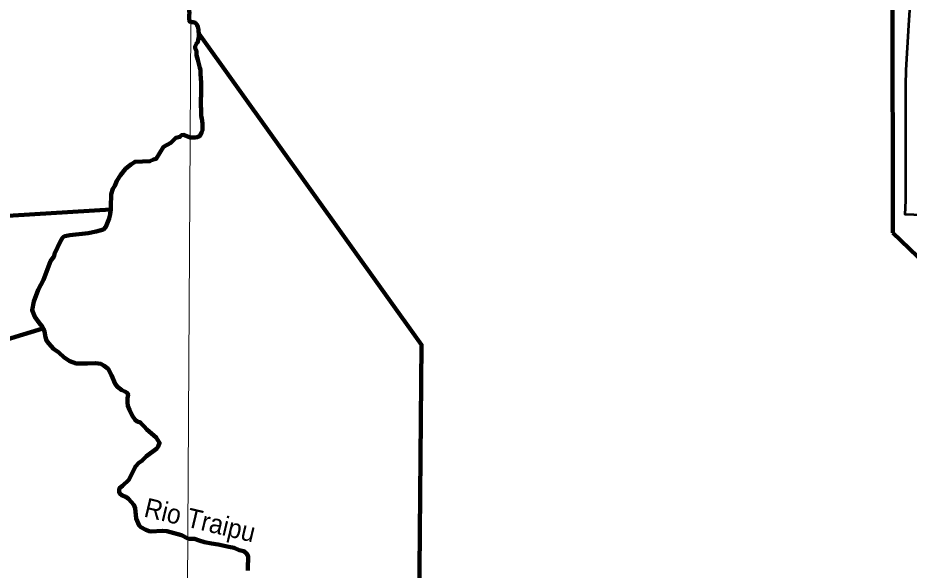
# Model space of a CAD drawing. Extents: x -1643653 to 4543381, y 1624270 to 13878484.
# Drawn here: x 714916 to 738063, y 8908730 to 8923080 of the extents above; entities that cross this region are included whole.
import ezdxf
from ezdxf.enums import TextEntityAlignment as Align

# ---------------------------------------------------------------- set-up
doc = ezdxf.new("R2010")
doc.units = 0
doc.header["$LTSCALE"] = 200
for name, color, linetype, lineweight in [('1', 7, 'Continuous', 13), ('24', 7, 'Continuous', 25), ('26', 7, 'Continuous', 106), ('28', 7, 'Continuous', 53), ('53', 7, 'Continuous', 106), ('60', 7, 'Continuous', 13), ('9', 7, 'Continuous', 90)]:
    doc.layers.add(name, color=color, linetype=linetype, lineweight=lineweight)
doc.layers.add('49', color=7, linetype='Continuous')

msp = doc.modelspace()

# ---------------------------------------------------------------- linework, layer by layer
at = {"layer": '1'}
msp.add_lwpolyline([(719978.9, 9023574.5), (719561.6, 8949232.2), (719215.6, 8890710.6)], dxfattribs=at)
at = {"layer": '24', "lineweight": 53}
for points in [[(719358.6, 8923326.6), (719372.1, 8923197), (719363, 8923148), (719367.5, 8923075.7), (719375.1, 8922983.9), (719405.7, 8922963.6)], [(719405.7, 8922963.6), (719467, 8922963.5), (719527.9, 8922947.8), (719573.3, 8922891.5), (719593.3, 8922845.5), (719608.1, 8922779.2), (719607.8, 8922728.2), (719612.5, 8922677.3), (719617.2, 8922621.2), (719616.8, 8922565.2), (719596.1, 8922509.3), (719590.6, 8922448.2), (719555.4, 8922413.6), (719520.2, 8922331.3), (719524.1, 8922280.4), (719553.5, 8922224.3), (719553.1, 8922173.4), (719552.7, 8922107.2), (719587.5, 8921989.8), (719627.2, 8921846.9), (719642, 8921780.6), (719656.8, 8921724.4), (719661.5, 8921663.3), (719661, 8921586.9), (719665.7, 8921535.9), (719670.4, 8921479.9), (719675.1, 8921423.8), (719674.7, 8921357.6), (719674.3, 8921301.6), (719673.9, 8921240.4), (719673.5, 8921184.4), (719673.1, 8921123.3), (719672.6, 8921057.1), (719672.1, 8920985.7), (719671.7, 8920929.7), (719671.3, 8920863.5), (719670.7, 8920782), (719675.3, 8920705.6), (719674.8, 8920644.4), (719674.4, 8920578.2), (719679.1, 8920527.2), (719693.9, 8920460.9), (719703.7, 8920399.8), (719708.3, 8920328.4), (719707.9, 8920272.4), (719707.5, 8920211.2), (719707.1, 8920155.2), (719681.3, 8920099.3), (719660.5, 8920043.4), (719629.7, 8920002.9), (719573.7, 8919982.9), (719517.6, 8919973.1), (719446.4, 8919968.4), (719388, 8919968.8)], [(719388, 8919968.8), (719217, 8920039.9), (719168.4, 8920030.7), (719126.8, 8919983.7), (719021.9, 8919963.8), (718888.7, 8919829.8), (718888.7, 8919829.8)], [(718888.7, 8919829.8), (718698.9, 8919728.1), (718508.1, 8919414.8), (718441.7, 8919396.1), (718342.3, 8919352.7), (717962.6, 8919341.8), (717850.2, 8919266.6), (717715.4, 8919155.6), (717584.3, 8918993), (717484.9, 8918843.2), (717433.5, 8918714), (717386.5, 8918633.6), (717343.6, 8918502.1), (717334.1, 8918168.6), (717316.4, 8917983.3), (717287.5, 8917863.5), (717202.1, 8917652.5), (717139.9, 8917584.2), (716949.9, 8917526.3), (716744.6, 8917482.9), (716262.7, 8917433.2), (716138.9, 8917405.7), (716105.4, 8917390.9), (716076.8, 8917365.2), (716021.3, 8917281.8), (715870.4, 8916945.9), (715855.1, 8916891.8), (715765.5, 8916761), (715585.2, 8916273.3), (715439.9, 8916014.5), (715332.6, 8915712.1), (715285.6, 8915483), (715360.4, 8915309.1), (715466.5, 8915151.7), (715544.8, 8915057.8), (715568.8, 8915033.9), (715582.8, 8914999.5)], [(715582.8, 8914999.5), (715607.3, 8914926.5), (715630.8, 8914782.1), (715664.2, 8914698.4), (715720.4, 8914621.3), (715841.4, 8914484.8), (715976.3, 8914382.9), (716121.9, 8914251.7), (716262.7, 8914158.2), (716430.6, 8914102.4), (716723.3, 8914098.2), (716931, 8914106.3), (717067.3, 8914089.8), (717160, 8914040), (717258.6, 8913960.8), (717350.2, 8913798.9), (717444.9, 8913569.6), (717500.7, 8913495.3), (717620.4, 8913403.7), (717696.9, 8913374.6), (717753.4, 8913338.3), (717771.3, 8913315.3), (717779.7, 8913284.7), (717767.4, 8913198.7), (717765.2, 8913088.6), (717776, 8913003.3), (717816.4, 8912891.5), (717881.6, 8912752), (717959.7, 8912633.8), (718012.2, 8912595.1), (718103.9, 8912566), (718108.4, 8912552.9), (718200.6, 8912462.7), (718263.8, 8912388), (718510.9, 8912180.7), (718595.9, 8912042.5), (718559.6, 8911942), (718525.1, 8911895.3), (718256.7, 8911695.7), (718139.8, 8911569.1), (718058.8, 8911518.2), (717971, 8911425.9), (717799.8, 8911079.5), (717637.2, 8910919.9), (717559.9, 8910863.9), (717548.7, 8910844.9), (717546.6, 8910765.8), (717564.2, 8910723.9), (717629.5, 8910673.2), (717717.9, 8910632.5), (717786.1, 8910583.9), (717932.5, 8910426.1), (717961.9, 8910338.5), (717987.1, 8910076.6), (718063.3, 8909892.7), (718110.2, 8909851.7), (718240.9, 8909774.5), (718323.8, 8909744.9), (718380.9, 8909735.3), (718665.9, 8909753.1), (718783.6, 8909747.4), (719169.5, 8909639.4), (719326.4, 8909556.3)], [(719326.4, 8909556.3), (719371.3, 8909542.5), (719371.3, 8909542.5), (719504.5, 8909548.1), (719504.5, 8909548.1), (719504.5, 8909548.1), (719626.5, 8909498.2)], [(719626.5, 8909498.2), (719765.2, 8909453.8), (719765.2, 8909453.8), (719765.2, 8909453.8), (719765.2, 8909453.8), (719948.4, 8909426.1), (719948.4, 8909426.1), (719948.4, 8909426.1), (720114.8, 8909398.4), (720114.8, 8909398.4), (720114.8, 8909398.4), (720392.3, 8909337.4), (720392.3, 8909337.4), (720392.3, 8909337.4), (720392.3, 8909337.4), (720531, 8909309.6), (720531, 8909309.6), (720531, 8909309.6), (720664.2, 8909248.6), (720780.7, 8909226.5), (720848.9, 8909167.8), (720879.1, 8909126.9), (720899.1, 8909075.8), (720898.7, 8909024.9), (720898.3, 8908963.8), (720892.8, 8908897.6), (720892.3, 8908831.3), (720886.9, 8908780.4), (720886.5, 8908724.4)]]:
    msp.add_lwpolyline(points, dxfattribs=at)
at = {"layer": '26'}
msp.add_line((737629.1, 8928921.3), (737637.3, 8917498.1), dxfattribs=at)
msp.add_lwpolyline([(737637.3, 8917498.1), (741487, 8913799.2), (751263.9, 8913799.2), (755491.7, 8914698), (756495.8, 8917341.8), (762467.6, 8919403.9), (760776.5, 8922153.4), (765744.2, 8926965), (762150.6, 8945735.5), (759238.1, 8946605.9)], dxfattribs=at)
at = {"layer": '28'}
msp.add_lwpolyline([(741408.6, 8915888.8), (739953, 8915879.4), (739975.5, 8917894.7), (737960, 8917973), (737974.2, 8918336.2), (737976.2, 8921330.6), (737981.7, 8921715.8), (738054.7, 8922885.5), (738115.5, 8923802.2), (738068.6, 8925272.7)], dxfattribs=at)
at = {"layer": '53'}
for points in [[(719358.6, 8923326.6), (719372.1, 8923197), (719363, 8923148), (719367.5, 8923075.7), (719375.1, 8922983.9), (719405.7, 8922963.6)], [(719358.6, 8923326.6), (719372.1, 8923197), (719363, 8923148), (719367.5, 8923075.7), (719375.1, 8922983.9), (719405.7, 8922963.6)], [(719358.6, 8923326.6), (719372.1, 8923197), (719363, 8923148), (719367.5, 8923075.7), (719375.1, 8922983.9), (719405.7, 8922963.6)], [(719405.7, 8922963.6), (719467, 8922963.5), (719527.9, 8922947.8), (719573.3, 8922891.5), (719593.3, 8922845.5), (719608.1, 8922779.2), (719607.8, 8922728.2), (719612.5, 8922677.3), (719617.2, 8922621.2), (719616.8, 8922565.2), (719596.1, 8922509.3), (719590.6, 8922448.2), (719555.4, 8922413.6), (719520.2, 8922331.3), (719524.1, 8922280.4), (719553.5, 8922224.3), (719553.1, 8922173.4), (719552.7, 8922107.2), (719587.5, 8921989.8), (719627.2, 8921846.9), (719642, 8921780.6), (719656.8, 8921724.4), (719661.5, 8921663.3), (719661, 8921586.9), (719665.7, 8921535.9), (719670.4, 8921479.9), (719675.1, 8921423.8), (719674.7, 8921357.6), (719674.3, 8921301.6), (719673.9, 8921240.4), (719673.5, 8921184.4), (719673.1, 8921123.3), (719672.6, 8921057.1), (719672.1, 8920985.7), (719671.7, 8920929.7), (719671.3, 8920863.5), (719670.7, 8920782), (719675.3, 8920705.6), (719674.8, 8920644.4), (719674.4, 8920578.2), (719679.1, 8920527.2), (719693.9, 8920460.9), (719703.7, 8920399.8), (719708.3, 8920328.4), (719707.9, 8920272.4), (719707.5, 8920211.2), (719707.1, 8920155.2), (719681.3, 8920099.3), (719660.5, 8920043.4), (719629.7, 8920002.9), (719573.7, 8919982.9), (719517.6, 8919973.1), (719446.4, 8919968.4), (719388, 8919968.8)], [(719405.7, 8922963.6), (719467, 8922963.5), (719527.9, 8922947.8), (719573.3, 8922891.5), (719593.3, 8922845.5), (719608.1, 8922779.2), (719607.8, 8922728.2), (719612.5, 8922677.3), (719617.2, 8922621.2), (719616.8, 8922565.2), (719596.1, 8922509.3), (719590.6, 8922448.2), (719555.4, 8922413.6), (719520.2, 8922331.3), (719524.1, 8922280.4), (719553.5, 8922224.3), (719553.1, 8922173.4), (719552.7, 8922107.2), (719587.5, 8921989.8), (719627.2, 8921846.9), (719642, 8921780.6), (719656.8, 8921724.4), (719661.5, 8921663.3), (719661, 8921586.9), (719665.7, 8921535.9), (719670.4, 8921479.9), (719675.1, 8921423.8), (719674.7, 8921357.6), (719674.3, 8921301.6), (719673.9, 8921240.4), (719673.5, 8921184.4), (719673.1, 8921123.3), (719672.6, 8921057.1), (719672.1, 8920985.7), (719671.7, 8920929.7), (719671.3, 8920863.5), (719670.7, 8920782), (719675.3, 8920705.6), (719674.8, 8920644.4), (719674.4, 8920578.2), (719679.1, 8920527.2), (719693.9, 8920460.9), (719703.7, 8920399.8), (719708.3, 8920328.4), (719707.9, 8920272.4), (719707.5, 8920211.2), (719707.1, 8920155.2), (719681.3, 8920099.3), (719660.5, 8920043.4), (719629.7, 8920002.9), (719573.7, 8919982.9), (719517.6, 8919973.1), (719446.4, 8919968.4), (719388, 8919968.8)], [(719405.7, 8922963.6), (719467, 8922963.5), (719527.9, 8922947.8), (719573.3, 8922891.5), (719593.3, 8922845.5), (719608.1, 8922779.2), (719607.8, 8922728.2), (719612.5, 8922677.3), (719617.2, 8922621.2), (719616.8, 8922565.2), (719596.1, 8922509.3), (719590.6, 8922448.2), (719555.4, 8922413.6), (719520.2, 8922331.3), (719524.1, 8922280.4), (719553.5, 8922224.3), (719553.1, 8922173.4), (719552.7, 8922107.2), (719587.5, 8921989.8), (719627.2, 8921846.9), (719642, 8921780.6), (719656.8, 8921724.4), (719661.5, 8921663.3), (719661, 8921586.9), (719665.7, 8921535.9), (719670.4, 8921479.9), (719675.1, 8921423.8), (719674.7, 8921357.6), (719674.3, 8921301.6), (719673.9, 8921240.4), (719673.5, 8921184.4), (719673.1, 8921123.3), (719672.6, 8921057.1), (719672.1, 8920985.7), (719671.7, 8920929.7), (719671.3, 8920863.5), (719670.7, 8920782), (719675.3, 8920705.6), (719674.8, 8920644.4), (719674.4, 8920578.2), (719679.1, 8920527.2), (719693.9, 8920460.9), (719703.7, 8920399.8), (719708.3, 8920328.4), (719707.9, 8920272.4), (719707.5, 8920211.2), (719707.1, 8920155.2), (719681.3, 8920099.3), (719660.5, 8920043.4), (719629.7, 8920002.9), (719573.7, 8919982.9), (719517.6, 8919973.1), (719446.4, 8919968.4), (719388, 8919968.8)], [(719388, 8919968.8), (719217, 8920039.9), (719168.4, 8920030.7), (719126.8, 8919983.7), (719021.9, 8919963.8), (718888.7, 8919829.8), (718888.7, 8919829.8)], [(719388, 8919968.8), (719217, 8920039.9), (719168.4, 8920030.7), (719126.8, 8919983.7), (719021.9, 8919963.8), (718888.7, 8919829.8), (718888.7, 8919829.8)], [(719388, 8919968.8), (719217, 8920039.9), (719168.4, 8920030.7), (719126.8, 8919983.7), (719021.9, 8919963.8), (718888.7, 8919829.8), (718888.7, 8919829.8)], [(718888.7, 8919829.8), (718698.9, 8919728.1), (718508.1, 8919414.8), (718441.7, 8919396.1), (718342.3, 8919352.7), (717962.6, 8919341.8), (717850.2, 8919266.6), (717715.4, 8919155.6), (717584.3, 8918993), (717484.9, 8918843.2), (717433.5, 8918714), (717386.5, 8918633.6), (717343.6, 8918502.1), (717334.1, 8918168.6), (717316.4, 8917983.3), (717287.5, 8917863.5), (717202.1, 8917652.5), (717139.9, 8917584.2), (716949.9, 8917526.3), (716744.6, 8917482.9), (716262.7, 8917433.2), (716138.9, 8917405.7), (716105.4, 8917390.9), (716076.8, 8917365.2), (716021.3, 8917281.8), (715870.4, 8916945.9), (715855.1, 8916891.8), (715765.5, 8916761), (715585.2, 8916273.3), (715439.9, 8916014.5), (715332.6, 8915712.1), (715285.6, 8915483), (715360.4, 8915309.1), (715466.5, 8915151.7), (715544.8, 8915057.8), (715568.8, 8915033.9), (715582.8, 8914999.5)], [(718888.7, 8919829.8), (718698.9, 8919728.1), (718508.1, 8919414.8), (718441.7, 8919396.1), (718342.3, 8919352.7), (717962.6, 8919341.8), (717850.2, 8919266.6), (717715.4, 8919155.6), (717584.3, 8918993), (717484.9, 8918843.2), (717433.5, 8918714), (717386.5, 8918633.6), (717343.6, 8918502.1), (717334.1, 8918168.6), (717316.4, 8917983.3), (717287.5, 8917863.5), (717202.1, 8917652.5), (717139.9, 8917584.2), (716949.9, 8917526.3), (716744.6, 8917482.9), (716262.7, 8917433.2), (716138.9, 8917405.7), (716105.4, 8917390.9), (716076.8, 8917365.2), (716021.3, 8917281.8), (715870.4, 8916945.9), (715855.1, 8916891.8), (715765.5, 8916761), (715585.2, 8916273.3), (715439.9, 8916014.5), (715332.6, 8915712.1), (715285.6, 8915483), (715360.4, 8915309.1), (715466.5, 8915151.7), (715544.8, 8915057.8), (715568.8, 8915033.9), (715582.8, 8914999.5)], [(718888.7, 8919829.8), (718698.9, 8919728.1), (718508.1, 8919414.8), (718441.7, 8919396.1), (718342.3, 8919352.7), (717962.6, 8919341.8), (717850.2, 8919266.6), (717715.4, 8919155.6), (717584.3, 8918993), (717484.9, 8918843.2), (717433.5, 8918714), (717386.5, 8918633.6), (717343.6, 8918502.1), (717334.1, 8918168.6), (717316.4, 8917983.3), (717287.5, 8917863.5), (717202.1, 8917652.5), (717139.9, 8917584.2), (716949.9, 8917526.3), (716744.6, 8917482.9), (716262.7, 8917433.2), (716138.9, 8917405.7), (716105.4, 8917390.9), (716076.8, 8917365.2), (716021.3, 8917281.8), (715870.4, 8916945.9), (715855.1, 8916891.8), (715765.5, 8916761), (715585.2, 8916273.3), (715439.9, 8916014.5), (715332.6, 8915712.1), (715285.6, 8915483), (715360.4, 8915309.1), (715466.5, 8915151.7), (715544.8, 8915057.8), (715568.8, 8915033.9), (715582.8, 8914999.5)], [(715582.8, 8914999.5), (715607.3, 8914926.5), (715630.8, 8914782.1), (715664.2, 8914698.4), (715720.4, 8914621.3), (715841.4, 8914484.8), (715976.3, 8914382.9), (716121.9, 8914251.7), (716262.7, 8914158.2), (716430.6, 8914102.4), (716723.3, 8914098.2), (716931, 8914106.3), (717067.3, 8914089.8), (717160, 8914040), (717258.6, 8913960.8), (717350.2, 8913798.9), (717444.9, 8913569.6), (717500.7, 8913495.3), (717620.4, 8913403.7), (717696.9, 8913374.6), (717753.4, 8913338.3), (717771.3, 8913315.3), (717779.7, 8913284.7), (717767.4, 8913198.7), (717765.2, 8913088.6), (717776, 8913003.3), (717816.4, 8912891.5), (717881.6, 8912752), (717959.7, 8912633.8), (718012.2, 8912595.1), (718103.9, 8912566), (718108.4, 8912552.9), (718200.6, 8912462.7), (718263.8, 8912388), (718510.9, 8912180.7), (718595.9, 8912042.5), (718559.6, 8911942), (718525.1, 8911895.3), (718256.7, 8911695.7), (718139.8, 8911569.1), (718058.8, 8911518.2), (717971, 8911425.9), (717799.8, 8911079.5), (717637.2, 8910919.9), (717559.9, 8910863.9), (717548.7, 8910844.9), (717546.6, 8910765.8), (717564.2, 8910723.9), (717629.5, 8910673.2), (717717.9, 8910632.5), (717786.1, 8910583.9), (717932.5, 8910426.1), (717961.9, 8910338.5), (717987.1, 8910076.6), (718063.3, 8909892.7), (718110.2, 8909851.7), (718240.9, 8909774.5), (718323.8, 8909744.9), (718380.9, 8909735.3), (718665.9, 8909753.1), (718783.6, 8909747.4), (719169.5, 8909639.4), (719326.4, 8909556.3)], [(715582.8, 8914999.5), (715607.3, 8914926.5), (715630.8, 8914782.1), (715664.2, 8914698.4), (715720.4, 8914621.3), (715841.4, 8914484.8), (715976.3, 8914382.9), (716121.9, 8914251.7), (716262.7, 8914158.2), (716430.6, 8914102.4), (716723.3, 8914098.2), (716931, 8914106.3), (717067.3, 8914089.8), (717160, 8914040), (717258.6, 8913960.8), (717350.2, 8913798.9), (717444.9, 8913569.6), (717500.7, 8913495.3), (717620.4, 8913403.7), (717696.9, 8913374.6), (717753.4, 8913338.3), (717771.3, 8913315.3), (717779.7, 8913284.7), (717767.4, 8913198.7), (717765.2, 8913088.6), (717776, 8913003.3), (717816.4, 8912891.5), (717881.6, 8912752), (717959.7, 8912633.8), (718012.2, 8912595.1), (718103.9, 8912566), (718108.4, 8912552.9), (718200.6, 8912462.7), (718263.8, 8912388), (718510.9, 8912180.7), (718595.9, 8912042.5), (718559.6, 8911942), (718525.1, 8911895.3), (718256.7, 8911695.7), (718139.8, 8911569.1), (718058.8, 8911518.2), (717971, 8911425.9), (717799.8, 8911079.5), (717637.2, 8910919.9), (717559.9, 8910863.9), (717548.7, 8910844.9), (717546.6, 8910765.8), (717564.2, 8910723.9), (717629.5, 8910673.2), (717717.9, 8910632.5), (717786.1, 8910583.9), (717932.5, 8910426.1), (717961.9, 8910338.5), (717987.1, 8910076.6), (718063.3, 8909892.7), (718110.2, 8909851.7), (718240.9, 8909774.5), (718323.8, 8909744.9), (718380.9, 8909735.3), (718665.9, 8909753.1), (718783.6, 8909747.4), (719169.5, 8909639.4), (719326.4, 8909556.3)], [(715582.8, 8914999.5), (715607.3, 8914926.5), (715630.8, 8914782.1), (715664.2, 8914698.4), (715720.4, 8914621.3), (715841.4, 8914484.8), (715976.3, 8914382.9), (716121.9, 8914251.7), (716262.7, 8914158.2), (716430.6, 8914102.4), (716723.3, 8914098.2), (716931, 8914106.3), (717067.3, 8914089.8), (717160, 8914040), (717258.6, 8913960.8), (717350.2, 8913798.9), (717444.9, 8913569.6), (717500.7, 8913495.3), (717620.4, 8913403.7), (717696.9, 8913374.6), (717753.4, 8913338.3), (717771.3, 8913315.3), (717779.7, 8913284.7), (717767.4, 8913198.7), (717765.2, 8913088.6), (717776, 8913003.3), (717816.4, 8912891.5), (717881.6, 8912752), (717959.7, 8912633.8), (718012.2, 8912595.1), (718103.9, 8912566), (718108.4, 8912552.9), (718200.6, 8912462.7), (718263.8, 8912388), (718510.9, 8912180.7), (718595.9, 8912042.5), (718559.6, 8911942), (718525.1, 8911895.3), (718256.7, 8911695.7), (718139.8, 8911569.1), (718058.8, 8911518.2), (717971, 8911425.9), (717799.8, 8911079.5), (717637.2, 8910919.9), (717559.9, 8910863.9), (717548.7, 8910844.9), (717546.6, 8910765.8), (717564.2, 8910723.9), (717629.5, 8910673.2), (717717.9, 8910632.5), (717786.1, 8910583.9), (717932.5, 8910426.1), (717961.9, 8910338.5), (717987.1, 8910076.6), (718063.3, 8909892.7), (718110.2, 8909851.7), (718240.9, 8909774.5), (718323.8, 8909744.9), (718380.9, 8909735.3), (718665.9, 8909753.1), (718783.6, 8909747.4), (719169.5, 8909639.4), (719326.4, 8909556.3)], [(719326.4, 8909556.3), (719371.3, 8909542.5), (719371.3, 8909542.5), (719504.5, 8909548.1), (719504.5, 8909548.1), (719504.5, 8909548.1), (719626.5, 8909498.2)], [(719326.4, 8909556.3), (719371.3, 8909542.5), (719371.3, 8909542.5), (719504.5, 8909548.1), (719504.5, 8909548.1), (719504.5, 8909548.1), (719626.5, 8909498.2)], [(719326.4, 8909556.3), (719371.3, 8909542.5), (719371.3, 8909542.5), (719504.5, 8909548.1), (719504.5, 8909548.1), (719504.5, 8909548.1), (719626.5, 8909498.2)], [(719626.5, 8909498.2), (719765.2, 8909453.8), (719765.2, 8909453.8), (719765.2, 8909453.8), (719765.2, 8909453.8), (719948.4, 8909426.1), (719948.4, 8909426.1), (719948.4, 8909426.1), (720114.8, 8909398.4), (720114.8, 8909398.4), (720114.8, 8909398.4), (720392.3, 8909337.4), (720392.3, 8909337.4), (720392.3, 8909337.4), (720392.3, 8909337.4), (720531, 8909309.6), (720531, 8909309.6), (720531, 8909309.6), (720664.2, 8909248.6), (720780.7, 8909226.5), (720848.9, 8909167.8), (720879.1, 8909126.9), (720899.1, 8909075.8), (720898.7, 8909024.9), (720898.3, 8908963.8), (720892.8, 8908897.6), (720892.3, 8908831.3), (720886.9, 8908780.4), (720886.5, 8908724.4)], [(719626.5, 8909498.2), (719765.2, 8909453.8), (719765.2, 8909453.8), (719765.2, 8909453.8), (719765.2, 8909453.8), (719948.4, 8909426.1), (719948.4, 8909426.1), (719948.4, 8909426.1), (720114.8, 8909398.4), (720114.8, 8909398.4), (720114.8, 8909398.4), (720392.3, 8909337.4), (720392.3, 8909337.4), (720392.3, 8909337.4), (720392.3, 8909337.4), (720531, 8909309.6), (720531, 8909309.6), (720531, 8909309.6), (720664.2, 8909248.6), (720780.7, 8909226.5), (720848.9, 8909167.8), (720879.1, 8909126.9), (720899.1, 8909075.8), (720898.7, 8909024.9), (720898.3, 8908963.8), (720892.8, 8908897.6), (720892.3, 8908831.3), (720886.9, 8908780.4), (720886.5, 8908724.4)], [(719626.5, 8909498.2), (719765.2, 8909453.8), (719765.2, 8909453.8), (719765.2, 8909453.8), (719765.2, 8909453.8), (719948.4, 8909426.1), (719948.4, 8909426.1), (719948.4, 8909426.1), (720114.8, 8909398.4), (720114.8, 8909398.4), (720114.8, 8909398.4), (720392.3, 8909337.4), (720392.3, 8909337.4), (720392.3, 8909337.4), (720392.3, 8909337.4), (720531, 8909309.6), (720531, 8909309.6), (720531, 8909309.6), (720664.2, 8909248.6), (720780.7, 8909226.5), (720848.9, 8909167.8), (720879.1, 8909126.9), (720899.1, 8909075.8), (720898.7, 8909024.9), (720898.3, 8908963.8), (720892.8, 8908897.6), (720892.3, 8908831.3), (720886.9, 8908780.4), (720886.5, 8908724.4)]]:
    msp.add_lwpolyline(points, dxfattribs=at)
at = {"layer": '60', "lineweight": 25}
msp.add_spline([(814781, 9009175.5), (814787.2, 9009173.4), (814796.9, 9009173.4), (814799.4, 9009172.4), (814805.1, 9009174.5), (814805.6, 9009176.5), (814811.7, 9009179.5), (814811.7, 9009179.5), (814801.5, 9009181), (814790.7, 9009181.5), (814784.1, 9009183.1), (814777.4, 9009185.1), (814778.4, 9009175.5)], degree=3, dxfattribs=at)
at = {"layer": '9'}
for p, q in [((702263.2, 8917164.2), (717332.2, 8918103.3)), ((710134.6, 8913345.1), (715561.4, 8915010.8))]:
    msp.add_line(p, q, dxfattribs=at)
for points in [[(719358.6, 8923326.6), (719372.1, 8923197), (719363, 8923148), (719367.5, 8923075.7), (719375.1, 8922983.9), (719405.7, 8922963.6)], [(719405.7, 8922963.6), (719467, 8922963.5), (719527.9, 8922947.8), (719573.3, 8922891.5), (719593.3, 8922845.5), (719608.1, 8922779.2), (719607.8, 8922728.2), (719612.5, 8922677.3), (719617.2, 8922621.2), (719616.8, 8922565.2), (719596.1, 8922509.3), (719590.6, 8922448.2), (719555.4, 8922413.6), (719520.2, 8922331.3), (719524.1, 8922280.4), (719553.5, 8922224.3), (719553.1, 8922173.4), (719552.7, 8922107.2), (719587.5, 8921989.8), (719627.2, 8921846.9), (719642, 8921780.6), (719656.8, 8921724.4), (719661.5, 8921663.3), (719661, 8921586.9), (719665.7, 8921535.9), (719670.4, 8921479.9), (719675.1, 8921423.8), (719674.7, 8921357.6), (719674.3, 8921301.6), (719673.9, 8921240.4), (719673.5, 8921184.4), (719673.1, 8921123.3), (719672.6, 8921057.1), (719672.1, 8920985.7), (719671.7, 8920929.7), (719671.3, 8920863.5), (719670.7, 8920782), (719675.3, 8920705.6), (719674.8, 8920644.4), (719674.4, 8920578.2), (719679.1, 8920527.2), (719693.9, 8920460.9), (719703.7, 8920399.8), (719708.3, 8920328.4), (719707.9, 8920272.4), (719707.5, 8920211.2), (719707.1, 8920155.2), (719681.3, 8920099.3), (719660.5, 8920043.4), (719629.7, 8920002.9), (719573.7, 8919982.9), (719517.6, 8919973.1), (719446.4, 8919968.4), (719388, 8919968.8)], [(741371.9, 8898310.2), (736775.3, 8899194.4), (730163.4, 8902976.8), (725291.2, 8902898), (725401.2, 8914588.3), (719613.1, 8922670.1)], [(719388, 8919968.8), (719217, 8920039.9), (719168.4, 8920030.7), (719126.8, 8919983.7), (719021.9, 8919963.8), (718888.7, 8919829.8), (718888.7, 8919829.8)], [(718888.7, 8919829.8), (718698.9, 8919728.1), (718508.1, 8919414.8), (718441.7, 8919396.1), (718342.3, 8919352.7), (717962.6, 8919341.8), (717850.2, 8919266.6), (717715.4, 8919155.6), (717584.3, 8918993), (717484.9, 8918843.2), (717433.5, 8918714), (717386.5, 8918633.6), (717343.6, 8918502.1), (717334.1, 8918168.6), (717327.9, 8918103.7)], [(717327.9, 8918103.7), (717316.4, 8917983.3), (717287.5, 8917863.5), (717202.1, 8917652.5), (717139.9, 8917584.2), (716949.9, 8917526.3), (716744.6, 8917482.9), (716262.7, 8917433.2), (716138.9, 8917405.7), (716105.4, 8917390.9), (716076.8, 8917365.2), (716021.3, 8917281.8), (715870.4, 8916945.9), (715855.1, 8916891.8), (715765.5, 8916761), (715585.2, 8916273.3), (715439.9, 8916014.5), (715332.6, 8915712.1), (715285.6, 8915483), (715360.4, 8915309.1), (715466.5, 8915151.7), (715544.8, 8915057.8), (715568.8, 8915033.9), (715582.8, 8914999.5), (715585.3, 8914991.8)], [(717327.9, 8918103.7), (717316.4, 8917983.3), (717287.5, 8917863.5), (717202.1, 8917652.5), (717139.9, 8917584.2), (716949.9, 8917526.3), (716744.6, 8917482.9), (716262.7, 8917433.2), (716138.9, 8917405.7), (716105.4, 8917390.9), (716076.8, 8917365.2), (716021.3, 8917281.8), (715870.4, 8916945.9), (715855.1, 8916891.8), (715765.5, 8916761), (715585.2, 8916273.3), (715439.9, 8916014.5), (715332.6, 8915712.1), (715285.6, 8915483), (715360.4, 8915309.1), (715466.5, 8915151.7), (715544.8, 8915057.8), (715568.8, 8915033.9), (715582.8, 8914999.5), (715585.3, 8914991.8)]]:
    msp.add_lwpolyline(points, dxfattribs=at)

# ---------------------------------------------------------------- texts
at = {"layer": '49', "width": 0.95}
msp.add_text('Rio Traipu', height=500, rotation=346.601, dxfattribs=at).set_placement((719591, 8909789.6), align=Align.CENTER)

doc.saveas('drawing.dxf')
